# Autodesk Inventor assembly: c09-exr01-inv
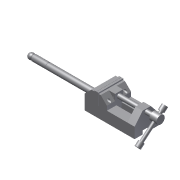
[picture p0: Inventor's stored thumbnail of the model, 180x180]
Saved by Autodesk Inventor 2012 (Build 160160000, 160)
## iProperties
Created: 2011-07
Part Number: c09-exr01-inv
Document SubType Name: Assembly
Designer: CadCim
Author: CadCim
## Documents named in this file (8)
- C:\Users\CadCim\Documents\SAILESH\inventor-2011-fact-prt\c09_inv_2011-prt\c09_inv_2012_prt\Exercises\c09_exr01_inv\c09-exr01-inv.iam
- C:\Users\CadCim\Documents\SAILESH\inventor-2011-fact-prt\c09_inv_2011-prt\c09_inv_2012_prt\Exercises\c09_exr01_inv\Base.ipt
- C:\Users\CadCim\Documents\SAILESH\inventor-2011-fact-prt\c09_inv_2011-prt\c09_inv_2012_prt\Exercises\c09_exr01_inv\Jaw Face.ipt
- C:\Users\CadCim\Documents\SAILESH\inventor-2011-fact-prt\c09_inv_2011-prt\c09_inv_2012_prt\Exercises\c09_exr01_inv\Movable Jaw.ipt
- C:\Users\CadCim\Documents\SAILESH\inventor-2011-fact-prt\c09_inv_2011-prt\c09_inv_2012_prt\Exercises\c09_exr01_inv\Safety Handle.ipt
- C:\Users\CadCim\Documents\SAILESH\inventor-2011-fact-prt\c09_inv_2011-prt\c09_inv_2012_prt\Exercises\c09_exr01_inv\Clamp Screw.ipt
- C:\Users\CadCim\Documents\SAILESH\inventor-2011-fact-prt\c09_inv_2011-prt\c09_inv_2012_prt\Exercises\c09_exr01_inv\Clamp Screw Handle.ipt
- C:\Users\CadCim\Documents\SAILESH\inventor-2011-fact-prt\c09_inv_2011-prt\c09_inv_2012_prt\Exercises\c09_exr01_inv\Handle Stop.ipt
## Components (9 placed, 7 different names)
1. Base:1 — Insert:1, Insert:2, Insert:3
2. Jaw Face:1 — Insert:1, Insert:2, Mate:1, Mate:2, Mate:5
3. Movable Jaw:1 — Mate:1, Mate:2, Mate:3, Insert:4, Insert:5, Insert:6
4. Safety Handle:1 — Insert:3
5. Clamp Screw:1 — Mate:3, Insert:4, Mate:4, Mate:6
6. Clamp Screw Handle:1 — Mate:4, Insert:7, Insert:8
7. Jaw Face:2 — Insert:5, Insert:6, Mate:5
8. Handle Stop:1 — Insert:7, Mate:6
9. Handle Stop:2 — Insert:8
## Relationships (14: Insert 8, Mate 6)
- Insert:1: Base:1 ↔ Jaw Face:1
- Insert:2: Base:1 ↔ Jaw Face:1
- Mate:1: Jaw Face:1 ↔ Movable Jaw:1
- Mate:2: Jaw Face:1 ↔ Movable Jaw:1
- Insert:3: Base:1 ↔ Safety Handle:1
- Mate:3: Movable Jaw:1 ↔ Clamp Screw:1
- Insert:4: Movable Jaw:1 ↔ Clamp Screw:1
- Mate:4: Clamp Screw:1 ↔ Clamp Screw Handle:1
- Insert:5: Movable Jaw:1 ↔ Jaw Face:2
- Insert:6: Movable Jaw:1 ↔ Jaw Face:2
- Mate:5: Jaw Face:1 ↔ Jaw Face:2
- Insert:7: Clamp Screw Handle:1 ↔ Handle Stop:1
- Insert:8: Clamp Screw Handle:1 ↔ Handle Stop:2
- Mate:6: Clamp Screw:1 ↔ Handle Stop:1
